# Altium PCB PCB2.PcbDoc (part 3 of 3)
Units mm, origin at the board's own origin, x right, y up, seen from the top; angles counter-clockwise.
Board outline 277.37 x 238.38 mm, 2 copper layers (Top Layer, Bottom Layer); 139 components, 149 nets, 593 pads, 86 vias.
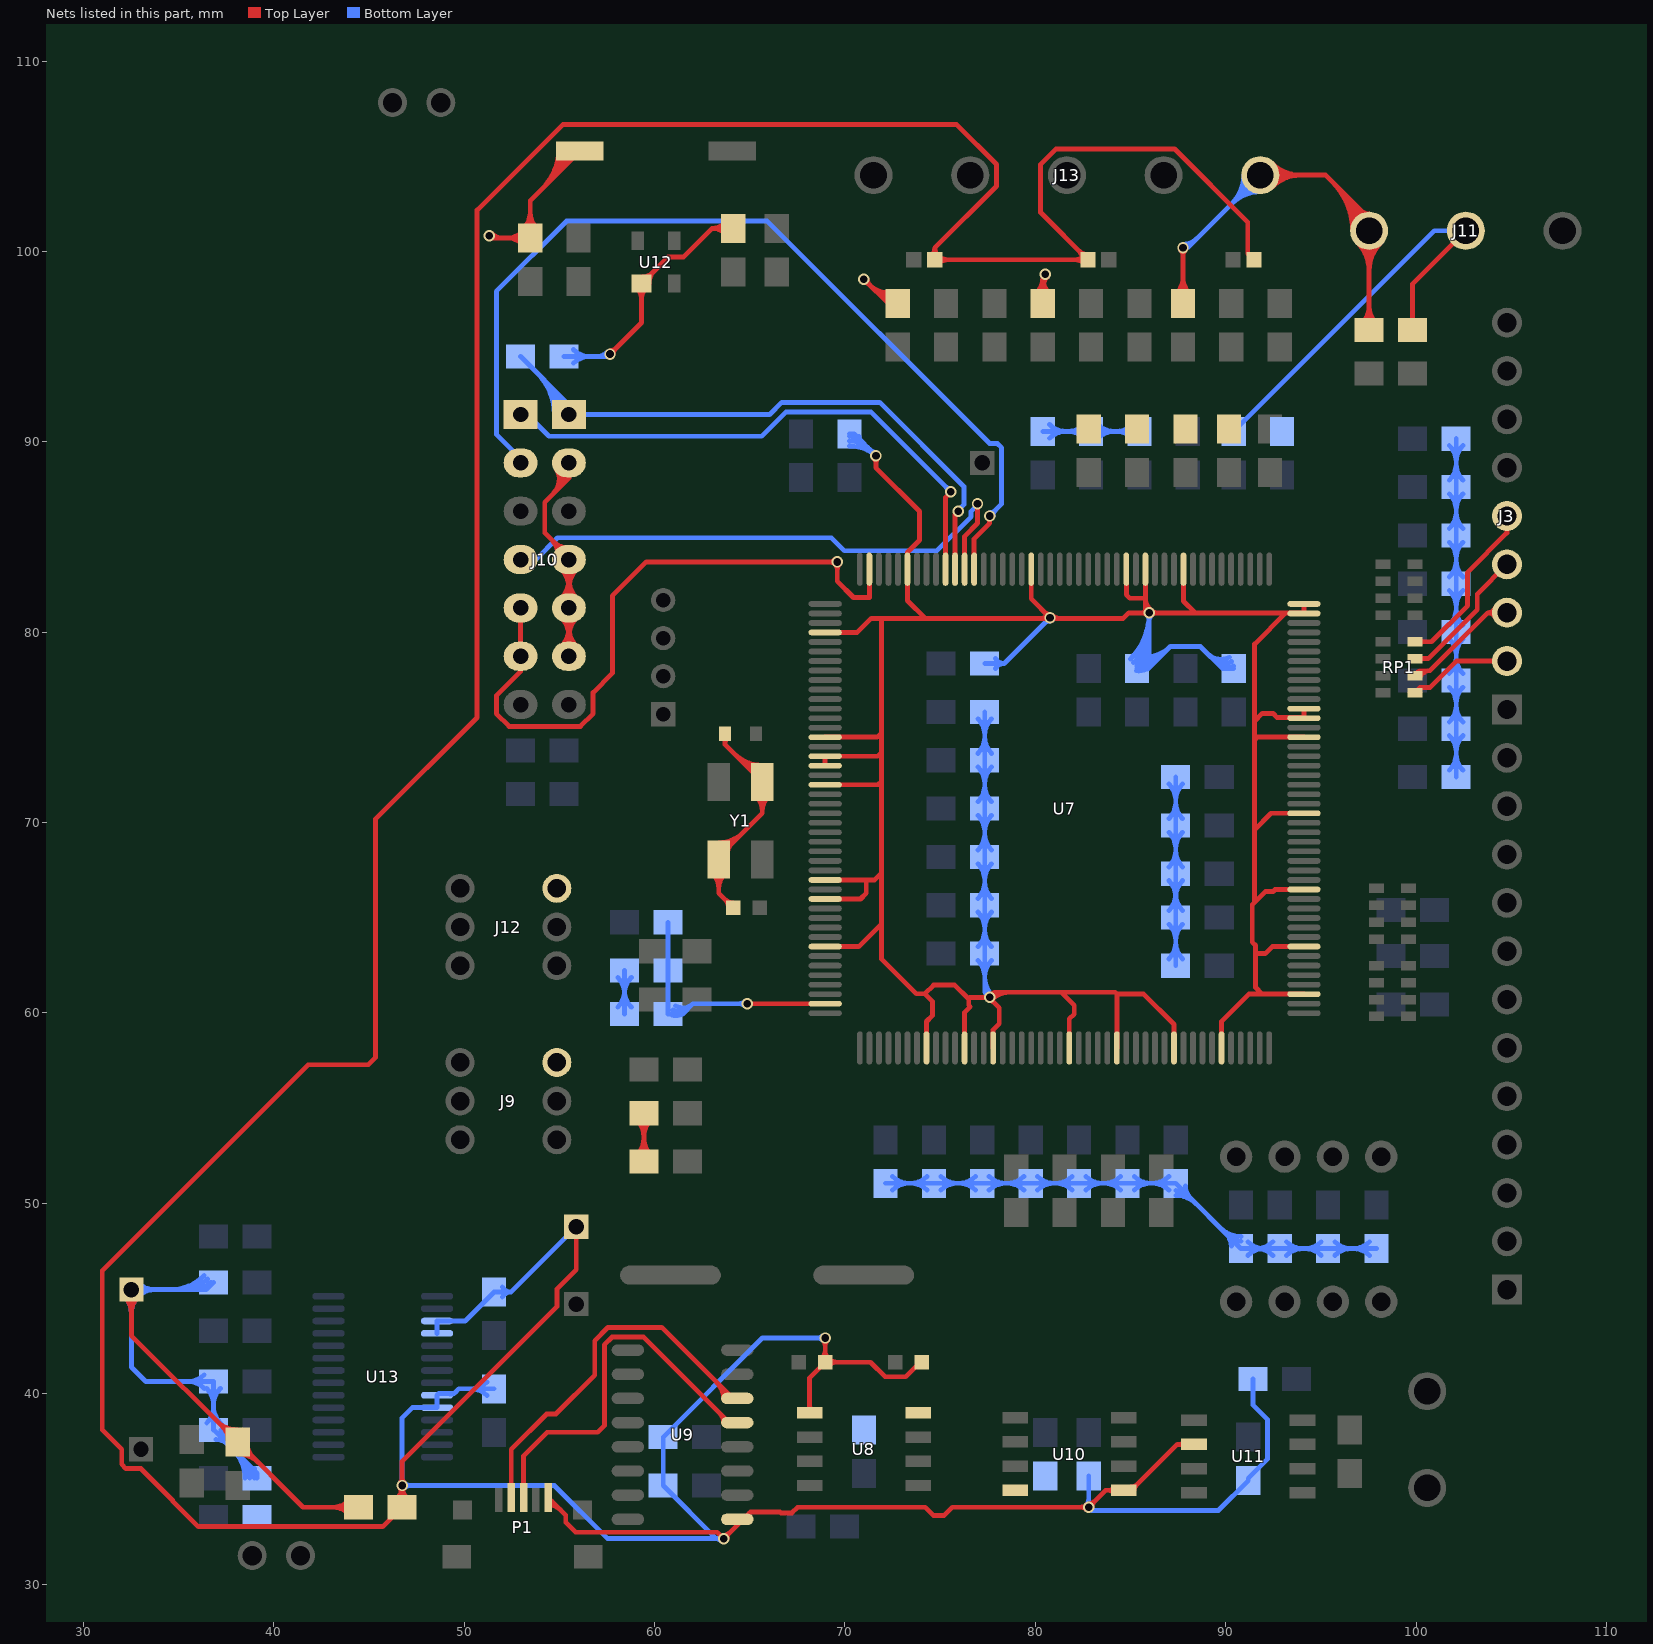
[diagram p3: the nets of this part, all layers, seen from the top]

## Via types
v1: diameter 0.6, hole 0.4, Top Layer to Bottom Layer, 86 vias

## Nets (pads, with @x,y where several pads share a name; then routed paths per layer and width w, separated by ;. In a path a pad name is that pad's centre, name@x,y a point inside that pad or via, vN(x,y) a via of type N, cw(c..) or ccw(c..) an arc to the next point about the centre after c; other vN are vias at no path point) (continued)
SN1: 3.1 C35.2 C37.2 C41.1 C42.1 C43.2 C47.2 C56.1 C64.1 D9.2 D10.2 D11.2 P1.5 R25.1 R59.1 U8.5 U9.1 U10.5 U11.2 U13.3 U13.4 U13.9 U13.10 | length 340.2
  Top Layer w0.254: R59.1@46.396,34.413 ccw(c45.704,35.179) v1(46.736,35.179) ; 46.736,35.814 v1(46.736,35.179) ; R59.1@47.076,34.413 cw(c47.768,35.179) v1(46.736,35.179) ; P1.5@54.416,34.544 55.335,33.625 55.335,33.236 55.851,32.72 63.292,32.72 v1(63.627,32.385) 65.024,33.782 ; 3.1@55.88,48.768 55.88,46.513 54.864,45.497 54.864,44.577 46.736,36.449 v1(46.736,35.179) ; U8.5@68.143,38.989 68.143,40.838 C41.1@68.961,41.656 ; v1(68.961,42.926) C41.1@68.961,41.656 ; C42.1@74.041,41.656 73.945,41.656 73.183,40.894 72.105,40.894 71.343,41.656 C41.1@68.961,41.656 ; U11.2@88.336,37.338 87.459,37.338 85.046,34.925 U10.5@84.638,34.925 83.693,34.925 v1(82.804,34.036) 75.639,34.036 75.212,33.609 74.648,33.609 74.221,34.036 67.511,34.036 67.211,33.736 66.647,33.736 66.601,33.782 65.024,33.782 ; D11.2@91.482,99.568 91.163,99.887 91.163,101.544 87.313,105.394 81.089,105.394 80.28,104.585 80.28,102.05 D10.2@82.762,99.568 D9.2@74.718,99.568 74.718,100.197 ; v1@46.614,35.301 ccw(c46.318,35.597) 46.736,35.597 ; v1@46.614,35.301 ccw(c46.318,35.597) 46.736,35.597 ; v1@46.614,35.301 ccw(c46.318,35.597) 46.736,35.597 ; v1@46.614,35.301 ccw(c46.318,35.597) 46.736,35.597 ; 46.736,34.761 cw(c47.154,34.761) 46.858,35.057 ccw(c47.154,34.761) 46.736,34.761 ; 46.736,34.761 ccw(c46.318,34.761) 46.614,35.057 cw(c46.318,34.761) 46.736,34.761 ; v1(46.736,35.179) R59.1@46.736,34.036 45.72,33.02 36.037,33.02 34.671,34.386 34.671,34.417 33.02,36.068 32.227,36.068 32.004,36.291 32.004,37.084 30.988,38.1 30.988,46.469 41.8,57.281 44.965,57.281 45.335,57.651 45.335,70.185 50.673,75.523 50.673,102.174 55.171,106.672 75.875,106.672 77.962,104.585 77.962,103.441 74.718,100.197 ; 46.736,35.597 ccw(c47.154,35.597) v1@46.858,35.301 ; 46.736,35.597 ccw(c47.154,35.597) v1@46.858,35.301 ; 46.736,35.597 ccw(c47.154,35.597) v1@46.858,35.301 ; 46.736,35.597 ccw(c47.154,35.597) v1@46.858,35.301 ; 63.922,32.68 cw(c63.627,32.976) 63.627,32.558 ccw(c63.627,32.976) 63.922,32.68 ; 63.922,32.68 ccw(c64.218,32.385) 63.8,32.385 cw(c64.218,32.385) 63.922,32.68 ; 65.024,33.782 ccw(c65.158,33.648) 65.019,33.519 cw(c65.158,33.648) 65.024,33.782 ; 68.143,39.407 cw(c67.725,39.407) 68.021,39.111 ccw(c67.725,39.407) 68.143,39.407 ; 68.143,39.407 ccw(c68.561,39.407) 68.265,39.111 cw(c68.561,39.407) 68.143,39.407 ; 68.961,42.269 cw(c68.348,42.269) 68.781,41.836 ccw(c68.348,42.269) 68.961,42.269 ; 68.961,42.269 ccw(c69.574,42.269) C41.1@69.141,41.836 ; 68.961,42.269 ccw(c69.574,42.269) C41.1@69.141,41.836 ; 68.961,42.508 cw(c69.379,42.508) 69.083,42.804 ccw(c69.379,42.508) 68.961,42.508 ; 68.961,42.508 ccw(c68.543,42.508) 68.839,42.804 cw(c68.543,42.508) 68.961,42.508 ; C41.1@69.141,41.836 ccw(c69.574,42.269) 69.574,41.656 ; C41.1@69.141,41.836 ccw(c69.574,42.269) 69.574,41.656 ; 69.574,41.656 ccw(c69.574,41.043) 69.141,41.476 cw(c69.574,41.043) 69.574,41.656 ; 74.718,100.197 cw(c74.13,100.197) 74.532,99.767 ccw(c74.13,100.197) 74.718,100.197 ; 74.718,100.197 ccw(c75.306,100.197) 74.904,99.767 cw(c75.306,100.197) 74.718,100.197 ; 75.377,99.568 cw(c75.377,100.227) 74.911,99.761 ccw(c75.377,100.227) 75.377,99.568 ; 75.377,99.568 ccw(c75.377,98.909) 74.911,99.375 cw(c75.377,98.909) 75.377,99.568 ; 82.103,99.568 cw(c82.103,98.909) 82.569,99.375 ccw(c82.103,98.909) 82.103,99.568 ; 82.103,99.568 ccw(c82.103,100.227) 82.569,99.761 cw(c82.103,100.227) 82.103,99.568 ; 82.296,100.034 cw(c81.83,99.568) 82.489,99.568 ccw(c81.83,99.568) 82.296,100.034 ; 82.296,100.034 ccw(c82.762,100.5) 82.762,99.841 cw(c82.762,100.5) 82.296,100.034 ; 82.386,34.036 cw(c82.386,33.618) 82.682,33.914 ccw(c82.386,33.618) 82.386,34.036 ; 82.386,34.036 ccw(c82.386,34.454) 82.682,34.158 cw(c82.386,34.454) 82.386,34.036 ; 83.099,34.331 cw(c82.804,34.627) 82.804,34.209 ccw(c82.804,34.627) 83.099,34.331 ; 83.099,34.331 ccw(c83.395,34.036) 82.977,34.036 cw(c83.395,34.036) 83.099,34.331 ; 83.845,34.925 cw(c83.845,34.507) 84.141,34.803 ccw(c83.845,34.507) 83.845,34.925 ; 83.845,34.925 ccw(c83.845,35.343) 84.141,35.047 cw(c83.845,35.343) 83.845,34.925 ; 87.543,37.338 cw(c87.543,36.92) 87.839,37.216 ccw(c87.543,36.92) 87.543,37.338 ; 87.543,37.338 ccw(c87.543,37.756) 87.839,37.46 cw(c87.543,37.756) 87.543,37.338 ; P1.5@54.416,34.163 cw(c54.416,33.243) 55.066,33.894 ccw(c54.416,33.243) P1.5@54.416,34.163 ; P1.5@54.416,34.417 cw(c54.416,34.11) 54.633,34.327 ccw(c54.416,34.11) P1.5@54.416,34.417 ; U10.5@85.013,35.098 ccw(c85.013,35.596) 85.365,35.244 cw(c85.013,35.596) U10.5@85.013,35.098 ; U10.5@85.186,34.925 cw(c85.523,34.925) 85.285,35.163 ccw(c85.523,34.925) U10.5@85.186,34.925
  Bottom Layer w0.254: U13.4@48.57,43.169 U13.3@48.57,43.819 50.042,43.819 C56.1@51.562,45.339 52.451,45.339 ; C64.1@51.562,40.259 49.721,40.259 49.475,40.013 48.664,40.013 U13.9@48.57,39.919 U13.10@48.57,39.269 47.27,39.269 46.736,38.735 v1(46.736,35.179) 54.737,35.179 57.531,32.385 63.246,32.385 ; 3.1@55.88,48.768 52.451,45.339 ; v1(63.627,32.385) 63.246,32.385 ; v1(68.961,42.926) 65.659,42.926 C35.2@60.452,37.719 C37.2@60.452,35.179 63.246,32.385 ; C47.2@82.804,35.687 v1(82.804,34.036) 82.977,33.863 89.616,33.863 C43.2@91.186,35.433 91.186,35.56 92.202,36.576 92.202,38.639 91.44,39.401 R25.1@91.44,40.767 ; 46.736,35.597 cw(c46.318,35.597) 46.614,35.301 ccw(c46.318,35.597) 46.736,35.597 ; 46.736,35.597 ccw(c47.154,35.597) v1@46.858,35.301 ; 46.736,35.597 ccw(c47.154,35.597) v1@46.858,35.301 ; v1@46.858,35.301 ccw(c47.154,35.597) 47.154,35.179 ; v1@46.858,35.301 ccw(c47.154,35.597) 47.154,35.179 ; 47.154,35.179 ccw(c47.154,34.761) 46.858,35.057 cw(c47.154,34.761) 47.154,35.179 ; 50.336,40.259 cw(c50.336,39.033) 51.203,39.9 ccw(c50.336,39.033) 50.336,40.259 ; 50.336,40.259 ccw(c50.336,41.485) 51.203,40.618 cw(c50.336,41.485) 50.336,40.259 ; 52.451,45.339 cw(c52.451,45.863) 52,45.597 ccw(c52.451,45.863) 52.451,45.339 ; 52.451,45.339 ccw(c52.451,44.815) 52,45.081 cw(c52.451,44.815) 52.451,45.339 ; 63.209,32.385 cw(c63.209,31.967) 63.505,32.263 ccw(c63.209,31.967) 63.209,32.385 ; 63.209,32.385 ccw(c63.209,32.803) 63.505,32.507 cw(c63.209,32.803) 63.209,32.385 ; 68.543,42.926 cw(c68.543,42.508) 68.839,42.804 ccw(c68.543,42.508) 68.543,42.926 ; 68.543,42.926 ccw(c68.543,43.344) 68.839,43.048 cw(c68.543,43.344) 68.543,42.926 ; 82.804,34.454 cw(c82.386,34.454) 82.682,34.158 ccw(c82.386,34.454) 82.804,34.454 ; 82.804,34.454 ccw(c83.222,34.454) 82.926,34.158 cw(c83.222,34.454) 82.804,34.454 ; U13.9@49.245,39.967 ccw(c49.245,40.412) 49.56,40.097 cw(c49.245,40.412) U13.9@49.245,39.967
SO1: J3.2 RP1.1 | length 5.9
  Top Layer w0.254: RP1.1@99.949,76.835 100.207,77.093 ; J3.2@104.775,78.486 102.123,78.486 100.73,77.093 100.207,77.093 ; 100.207,77.093 ccw(c100.304,76.996) 100.196,76.911 cw(c100.304,76.996) 100.207,77.093
SO2: J3.3 RP1.2 | length 10.7
  Top Layer w0.254: RP1.2@99.949,77.724 100.207,77.982 ; J3.3@104.775,81.026 103.774,81.026 ; 100.207,77.982 ccw(c100.304,77.885) 100.196,77.8 cw(c100.304,77.885) 100.207,77.982 ; 100.207,77.982 100.73,77.982 ; 100.73,77.982 ccw(c100.73,77.392) 100.208,77.667 cw(c100.73,77.392) 100.73,77.982 ; 100.73,77.982 103.774,81.026 ; 103.774,81.026 cw(c103.774,80.598) 104.168,80.766 ccw(c103.774,80.598) 103.774,81.026 ; 103.774,81.026 ccw(c103.774,81.454) 104.168,81.286 cw(c103.774,81.454) 103.774,81.026 ; RP1.2@99.983,77.785 cw(c100.309,77.613) 100.309,77.982 ccw(c100.309,77.613) RP1.2@99.983,77.785
SO3: J3.4 RP1.3 | length 8.3
  Top Layer w0.254: RP1.3@99.949,78.613 100.643,78.613 103.217,81.187 103.217,82.008 J3.4@104.775,83.566 ; 100.396,78.613 cw(c100.396,78.91) 100.186,78.7 ccw(c100.396,78.91) 100.396,78.613 ; 100.396,78.613 ccw(c100.396,78.316) 100.186,78.526 cw(c100.396,78.316) 100.396,78.613
SPEED: C54.2 J11.2 R23.1 | length 22.9
  Top Layer w0.254: C54.2@99.822,95.885 99.822,98.298 J11.2@102.616,101.092
  Bottom Layer w0.254: R23.1@90.424,90.551 100.965,101.092 J11.2@102.616,101.092
START: C55.2 R44.2 R45.2 U7.131 | length 20
  Top Layer w0.254: v1(64.86,60.489) U7.131@68.959,60.489
  Bottom Layer w0.254: R44.2@60.706,64.77 C55.2@60.706,62.23 R45.2@60.706,59.944 61.468,59.944 62.013,60.489 ; v1(64.86,60.489) 62.013,60.489 ; 62.013,60.489 cw(c61.484,61.018) 61.096,60.378 ccw(c61.484,61.018) 62.013,60.489 ; 64.442,60.489 cw(c64.442,60.071) 64.738,60.367 ccw(c64.442,60.071) 64.442,60.489 ; 64.442,60.489 ccw(c64.442,60.907) 64.738,60.611 cw(c64.442,60.907) 64.442,60.489 ; R45.2@60.833,59.944 ccw(c61.139,60.448) 61.555,60.031 cw(c61.139,60.448) R45.2@60.833,59.944 ; R45.2@60.965,60.161 ccw(c61.311,60.733) 61.784,60.26 cw(c61.311,60.733) R45.2@60.965,60.161
T\R\S\T\N\: J10.2 R28.1 U7.78 | length 44.2
  Top Layer w0.254: U7.78@75.784,83.314 v1@75.784,86.198
  Bottom Layer w0.254: R28.1@52.959,94.488 J10.2@55.499,91.948 ; v1(75.946,86.36) 75.946,86.395 76.246,86.695 76.246,87.658 71.829,92.075 66.688,92.075 66.053,91.44 J10.2@55.499,91.44 ; J10.2@55.499,91.44 ccw(c54.273,91.44) 55.14,92.307 cw(c54.273,91.44) J10.2@55.499,91.44 ; 53.839,93.608 cw(c51.671,91.44) 54.737,91.44 ccw(c51.671,91.44) 53.839,93.608 ; 54.273,93.174 cw(c52.538,91.44) 54.991,91.44 ccw(c52.538,91.44) 54.273,93.174 ; 54.706,92.741 cw(c53.405,91.44) 55.245,91.44 ccw(c53.405,91.44) 54.706,92.741
TCK: J10.9 J10.11 U7.87 | length 38
  Top Layer w0.254: J10.9@52.959,81.28 J10.11@52.959,78.74 52.959,77.943 51.689,76.673 51.689,75.727 52.359,75.057 56.099,75.057 56.769,75.727 56.769,76.83 57.785,77.846 57.785,81.915 59.563,83.693 v1(69.596,83.693) 69.596,82.677 70.448,81.825 71.284,81.825 U7.87@71.284,83.314 ; 69.178,83.693 cw(c69.178,83.275) v1@69.474,83.571 ; 69.178,83.693 ccw(c69.178,84.111) 69.474,83.815 cw(c69.178,84.111) 69.178,83.693 ; 69.178,83.693 cw(c69.178,83.275) v1@69.474,83.571 ; v1@69.474,83.571 cw(c69.178,83.275) 69.596,83.275 ; v1@69.474,83.571 cw(c69.178,83.275) 69.596,83.275 ; 69.596,83.275 cw(c70.014,83.275) 69.718,83.571 ccw(c70.014,83.275) 69.596,83.275
TDI: J10.3 U7.76 | length 50.8
  Top Layer w0.254: U7.76@76.784,83.314 76.784,84.912 77.597,85.725 v1(77.597,86.106)
  Bottom Layer w0.254: J10.3@52.959,88.9 52.959,89.123 51.689,90.393 51.689,97.917 55.372,101.6 65.913,101.6 77.597,89.916 78.009,89.916 78.232,89.693 78.232,86.741 v1(77.597,86.106) ; 77.892,86.401 cw(c77.597,86.697) 77.597,86.279 ccw(c77.597,86.697) 77.892,86.401 ; 77.892,86.401 ccw(c78.188,86.106) 77.77,86.106 cw(c78.188,86.106) 77.892,86.401
TDO: J10.7 U7.77 | length 29.7
  Top Layer w0.254: U7.77@76.284,83.314 76.284,85.047 76.962,85.725 v1(76.962,86.741)
  Bottom Layer w0.254: J10.7@52.959,83.82 53.756,83.82 54.899,84.963 69.289,84.963 69.97,84.282 74.831,84.282 76.627,86.078 76.627,86.358 76.962,86.693 v1(76.962,86.741)
TEMP: J3.5 RP1.4 | length 10
  Top Layer w0.254: RP1.4@99.949,79.502 100.813,79.502 102.709,81.398 102.709,83.152 104.775,85.218 J3.5@104.775,86.106 ; 100.396,79.502 cw(c100.396,79.799) 100.186,79.589 ccw(c100.396,79.799) 100.396,79.502 ; 100.396,79.502 ccw(c100.396,79.205) 100.186,79.415 cw(c100.396,79.205) 100.396,79.502
TMS: J10.1 U7.79 | length 30.8
  Top Layer w0.254: U7.79@75.284,83.314 75.284,87.095 v1(75.565,87.376)
  Bottom Layer w0.254: J10.1@52.959,91.44 53.309,91.44 54.452,90.297 65.628,90.297 66.898,91.567 71.374,91.567 v1(75.565,87.376) ; 75.27,87.671 cw(c74.974,87.376) 75.392,87.376 ccw(c74.974,87.376) 75.27,87.671 ; 75.27,87.671 ccw(c75.565,87.967) 75.565,87.549 cw(c75.565,87.967) 75.27,87.671
UD+: P1.3 U9.5 | length 21.5
  Top Layer w0.254: P1.3@53.116,34.544 53.116,36.733 54.356,37.973 57.015,37.973 57.362,38.32 57.362,42.573 57.761,42.972 59.425,42.972 63.916,38.481 U9.5@64.343,38.481 ; 63.411,38.986 cw(c62.905,38.481) 63.62,38.481 ccw(c62.905,38.481) 63.411,38.986
UD-: P1.2 U9.6 | length 22.3
  Top Layer w0.254: P1.2@52.466,34.544 52.466,37.076 54.325,38.935 54.815,38.935 56.854,40.974 56.854,42.783 57.551,43.48 60.371,43.48 64.1,39.751 U9.6@64.343,39.751 ; 63.281,40.57 cw(c62.461,39.751) 63.62,39.751 ccw(c62.461,39.751) 63.281,40.57 ; 63.714,40.137 cw(c63.329,39.751) 63.874,39.751 ccw(c63.329,39.751) 63.714,40.137
VSS: 5.1 C25.1 C26.1 C27.2 C28.1 C29.1 C30.1 C31.1 C32.1 C33.1 C34.2 C36.1 C38.1 C39.2 C40.2 C44.1 C45.2 C46.1 C48.1 C49.1 C50.2 C51.2 C52.2 C53.1 C54.1 C55.1 C57.2 C58.1 C59.1 C60.1 C61.1 C62.1 C63.1 C65.2 C66.1 C67.1 C68.2 C69.1 C70.1 C71.1 C72.1 C73.1 C74.1 C75.1 C76.1 C77.1 C78.1 C79.1 C80.1 C81.1 C82.1 C83.1 C84.1 C85.1 D12.2 J9.1 J10.4 J10.8 J10.10 J10.12 J11.1 J12.1 J13.5 R28.2 R33.1 R34.1 R38.1 R39.1 R40.1 R41.1 R45.1 R47.1 R59.2 S1.2 U7.3 U7.8 U7.14 U7.22 U7.30 U7.32 U7.33 U7.43 U7.44 U7.54 U7.58 U7.60 U7.70 U7.83 U7.92 U7.103 U7.105 U7.106 U7.108 U7.118 U7.120 U7.125 U7.140 U7.144 U7.147 U7.155 U7.160 U7.166 U7.171 U8.4 U10.4 U12.1 Y1.2 Y1.4 | length 884.1
  Top Layer w0.254: 5.1@32.512,45.466 32.512,43.053 D12.2@38.1,37.465 41.529,34.036 R59.2@44.45,34.036 ; R59.2@43.964,33.677 ccw(c43.097,32.81) 43.097,34.036 ccw(c43.097,35.262) R59.2@43.964,34.395 ; v1@51.435,100.711 C52.2@53.467,100.711 53.467,102.679 S1.2@56.071,105.283 ; J10.12@55.499,78.74 J10.10@55.499,81.28 J10.8@55.499,83.82 55.499,83.947 54.229,85.217 54.229,86.833 55.499,88.103 J10.4@55.499,88.9 ; v1(57.658,94.615) 59.311,96.268 U12.1@59.311,98.316 60.705,99.71 61.514,99.71 63.023,101.219 ; C49.1@59.436,52.197 R33.1@59.436,54.737 ; C40.2@63.703,74.676 63.703,74.092 Y1.4@65.659,72.136 65.659,70.492 63.373,68.206 Y1.2@63.373,68.072 63.373,66.294 C39.2@64.135,65.532 ; C53.1@64.135,101.219 63.023,101.219 ; U7.125@68.959,63.489 70.728,63.489 71.928,64.689 ; U7.120@68.959,65.989 70.815,65.989 71.12,66.294 71.12,66.883 ; U7.118@68.959,66.989 71.561,66.989 71.928,67.356 ; U7.108@68.959,71.989 71.735,71.989 71.928,72.182 ; U7.106@68.959,72.989 U7.105@68.959,73.489 71.711,73.489 71.928,73.706 ; U7.103@68.959,74.489 71.695,74.489 71.928,74.722 ; U7.92@68.959,79.989 70.644,79.989 ; 70.652,79.997 71.381,80.726 71.882,80.726 ; v1(70.993,98.552) 72.263,97.282 C61.1@72.771,97.282 ; v1(71.628,89.281) 71.628,88.646 73.914,86.36 73.914,84.836 73.284,84.206 U7.83@73.284,83.314 73.284,81.656 74.214,80.726 ; U7.140@74.284,58.164 74.284,59.552 74.595,59.863 74.595,60.607 74.196,61.006 ; U7.144@76.284,58.164 76.284,60.028 76.581,60.325 76.5,60.406 76.5,60.734 75.766,61.468 74.658,61.468 74.196,61.006 ; 76.577,60.811 v1@77.566,60.811 ; U7.147@77.784,58.164 77.784,59.115 78.105,59.436 78.105,60.272 v1@77.566,60.811 ; U7.70@79.784,83.314 79.784,81.76 v1(80.772,80.772) v1@80.818,80.726 ; C62.1@80.391,97.282 v1@80.391,98.679 ; v1@80.991,80.726 81.915,80.726 ; U7.155@81.784,58.164 81.784,59.686 82.042,59.944 82.042,60.399 81.354,61.087 ; U7.160@84.284,58.164 84.284,61.004 ; U7.60@84.784,83.314 84.784,81.967 84.963,81.788 85.784,81.788 ; U7.58@85.784,83.314 85.784,81.788 ; U7.166@87.284,58.164 87.284,59.401 85.681,61.004 84.284,61.004 ; C63.1@87.757,97.282 v1(87.757,100.203) ; U7.54@87.784,83.314 87.784,81.634 88.398,81.02 ; U7.171@89.784,58.164 89.784,59.558 91.215,60.989 91.845,60.989 ; J13.5@91.821,104.013 95.25,104.013 97.536,101.727 J11.1@97.536,101.092 C54.1@97.536,95.885 ; 92.59,66.481 92.484,66.375 92.075,66.375 91.526,65.827 ; 92.598,66.489 U7.14@94.109,66.489 ; U7.3@94.109,60.989 91.919,60.989 91.567,61.341 91.567,63.119 ; U7.8@94.109,63.489 92.445,63.489 92.075,63.119 91.567,63.119 ; U7.22@94.109,70.489 92.379,70.489 91.521,69.631 ; U7.30@94.109,74.489 91.669,74.489 91.521,74.341 ; U7.33@94.109,75.958 94.109,75.52 92.702,75.52 92.484,75.738 91.92,75.738 91.521,75.339 ; U7.44@94.109,81.489 94.109,81.02 93.164,81.02 ; 95.597,103.666 cw(c93.022,101.092) J11.1@96.663,101.092 ; 96.03,103.233 cw(c93.89,101.092) J11.1@96.917,101.092 ; 96.464,102.799 cw(c94.757,101.092) J11.1@97.171,101.092 ; 96.897,102.366 cw(c95.624,101.092) J11.1@97.425,101.092 ; J11.1@96.919,100.475 cw(c95.428,98.984) 97.536,98.984 cw(c99.644,98.984) J11.1@98.153,100.475 ; J11.1@97.098,100.654 cw(c96.042,99.598) 97.536,99.598 cw(c99.03,99.598) J11.1@97.974,100.654 ; 97.13,102.133 ccw(c97.536,102.54) J11.1@97.536,101.965 ; 32.512,44.24 cw(c33.738,44.24) 32.871,45.107 ccw(c33.738,44.24) 32.512,44.24 ; 32.512,44.24 ccw(c31.286,44.24) 32.153,45.107 cw(c31.286,44.24) 32.512,44.24 ; 52.241,100.711 cw(c52.241,99.485) 53.108,100.352 ccw(c52.241,99.485) 52.241,100.711 ; 52.241,100.711 ccw(c52.241,101.937) 53.108,101.07 cw(c52.241,101.937) 52.241,100.711 ; 53.467,102.064 cw(c52.241,102.064) 53.108,101.197 ccw(c52.241,102.064) 53.467,102.064 ; 53.467,102.064 ccw(c54.693,102.064) 53.826,101.197 cw(c54.693,102.064) 53.467,102.064 ; 55.499,79.66 cw(c54.579,79.66) 55.23,79.009 ccw(c54.579,79.66) 55.499,79.66 ; 55.499,79.66 ccw(c56.419,79.66) 55.768,79.009 cw(c56.419,79.66) 55.499,79.66 ; 55.499,79.747 cw(c57.032,79.747) 55.948,80.831 ccw(c57.032,79.747) 55.499,79.747 ; 55.499,79.747 ccw(c53.966,79.747) 55.05,80.831 cw(c53.966,79.747) 55.499,79.747 ; 55.499,80.273 cw(c53.966,80.273) 55.05,79.189 ccw(c53.966,80.273) 55.499,80.273 ; 55.499,80.273 ccw(c57.032,80.273) 55.948,79.189 cw(c57.032,80.273) 55.499,80.273 ; 55.499,80.36 cw(c56.419,80.36) 55.768,81.011 ccw(c56.419,80.36) 55.499,80.36 ; 55.499,80.36 ccw(c54.579,80.36) 55.23,81.011 cw(c54.579,80.36) 55.499,80.36 ; 55.499,82.2 cw(c54.579,82.2) 55.23,81.549 ccw(c54.579,82.2) 55.499,82.2 ; 55.499,82.2 ccw(c56.419,82.2) 55.768,81.549 cw(c56.419,82.2) 55.499,82.2 ; 55.499,82.287 cw(c57.032,82.287) 55.948,83.371 ccw(c57.032,82.287) 55.499,82.287 ; 55.499,82.287 ccw(c53.966,82.287) 55.05,83.371 cw(c53.966,82.287) 55.499,82.287 ; 55.499,82.813 cw(c53.966,82.813) 55.05,81.729 ccw(c53.966,82.813) 55.499,82.813 ; 55.499,82.813 ccw(c57.032,82.813) 55.948,81.729 cw(c57.032,82.813) 55.499,82.813 ; 55.499,82.9 cw(c56.419,82.9) 55.768,83.551 ccw(c56.419,82.9) 55.499,82.9 ; 55.499,82.9 ccw(c54.579,82.9) 55.23,83.551 cw(c54.579,82.9) 55.499,82.9 ; 57.953,94.91 cw(c57.658,95.206) 57.658,94.788 ccw(c57.658,95.206) 57.953,94.91 ; 57.953,94.91 ccw(c58.249,94.615) 57.831,94.615 cw(c58.249,94.615) 57.953,94.91 ; 59.311,97.476 cw(c60.151,97.476) 59.557,98.07 ccw(c60.151,97.476) 59.311,97.476 ; 59.311,97.476 ccw(c58.471,97.476) 59.065,98.07 cw(c58.471,97.476) 59.311,97.476 ; 59.436,53.423 cw(c58.21,53.423) 59.077,52.556 ccw(c58.21,53.423) 59.436,53.423 ; 59.436,53.423 ccw(c60.662,53.423) 59.795,52.556 cw(c60.662,53.423) 59.436,53.423 ; 59.436,53.511 cw(c60.662,53.511) 59.795,54.378 ccw(c60.662,53.511) 59.436,53.511 ; 59.436,53.511 ccw(c58.21,53.511) 59.077,54.378 cw(c58.21,53.511) 59.436,53.511 ; 63.023,101.219 cw(c63.023,100.256) 63.751,100.886 ccw(c63.023,100.256) 63.023,101.219 ; 63.023,101.219 ccw(c63.023,102.182) 63.751,101.552 cw(c63.023,102.182) 63.023,101.219 ; 63.373,66.53 cw(c64.515,66.53) 63.707,67.338 ccw(c64.515,66.53) 63.373,66.53 ; 63.373,66.53 ccw(c62.231,66.53) 63.039,67.338 cw(c62.231,66.53) 63.373,66.53 ; 63.701,65.966 cw(c63.268,65.532) 63.881,65.532 ccw(c63.268,65.532) 63.701,65.966 ; 63.701,65.966 ccw(c64.135,66.399) 64.135,65.786 cw(c64.135,66.399) 63.701,65.966 ; 63.703,74.153 cw(c64.163,74.153) 63.838,74.478 ccw(c64.163,74.153) 63.703,74.153 ; 63.703,74.153 ccw(c63.243,74.153) 63.568,74.478 cw(c63.243,74.153) 63.703,74.153 ; 65.659,70.594 cw(c66.801,70.594) 65.993,71.402 ccw(c66.801,70.594) 65.659,70.594 ; 65.659,70.594 ccw(c64.517,70.594) 65.325,71.402 cw(c64.517,70.594) 65.659,70.594 ; 71.288,98.257 cw(c71.584,98.552) 71.166,98.552 ccw(c71.584,98.552) 71.288,98.257 ; 71.288,98.257 ccw(c70.993,97.961) 70.993,98.379 cw(c70.993,97.961) 71.288,98.257 ; 71.628,88.863 cw(c72.046,88.863) 71.75,89.159 ccw(c72.046,88.863) 71.628,88.863 ; 71.628,88.863 ccw(c71.21,88.863) 71.506,89.159 cw(c71.21,88.863) 71.628,88.863 ; 71.882,80.726 71.928,80.68 71.928,74.722 ; 71.882,80.726 74.214,80.726 ; 71.928,64.689 71.928,62.819 73.741,61.006 74.196,61.006 ; 71.928,64.689 71.928,67.356 ; 71.928,67.356 71.928,72.182 ; 71.928,72.182 71.928,73.706 ; 71.928,73.706 71.928,74.722 ; 74.214,80.726 v1@80.818,80.726 ; v1@77.566,60.811 77.842,61.087 81.354,61.087 ; v1@80.391,98.635 cw(c79.165,98.635) 80.032,97.768 ccw(c79.165,98.635) v1@80.391,98.635 ; v1@80.391,98.635 ccw(c81.617,98.635) 80.75,97.768 cw(c81.617,98.635) v1@80.391,98.635 ; 80.477,81.067 cw(c80.181,80.772) 80.599,80.772 ccw(c80.181,80.772) 80.477,81.067 ; 80.477,81.067 ccw(c80.772,81.363) 80.772,80.945 cw(c80.772,81.363) 80.477,81.067 ; v1@80.818,80.726 81.915,80.726 ; v1@80.894,80.65 cw(c81.079,80.465) 81.079,80.726 ; v1@80.894,80.65 cw(c81.079,80.465) 81.079,80.726 ; v1@80.894,80.65 cw(c81.079,80.465) 81.079,80.726 ; v1@80.894,80.65 cw(c81.079,80.465) 81.079,80.726 ; v1@80.894,80.894 ccw(c81.301,81.301) 81.301,80.726 ; v1@80.894,80.894 ccw(c81.301,81.301) 81.301,80.726 ; v1@80.894,80.894 ccw(c81.301,81.301) 81.301,80.726 ; v1@80.894,80.894 ccw(c81.301,81.301) 81.301,80.726 ; 81.354,61.087 84.201,61.087 84.284,61.004 ; 81.915,80.726 84.61,80.726 84.904,81.02 v1@86.112,81.02 ; 85.784,81.788 ccw(c86.584,81.788) 86.087,81.161 cw(c86.584,81.788) 85.784,81.788 ; 85.784,81.788 85.784,81.348 v1@86.112,81.02 ; v1@86.112,81.02 88.398,81.02 ; 87.757,98.635 cw(c86.531,98.635) 87.398,97.768 ccw(c86.531,98.635) 87.757,98.635 ; 87.757,98.635 ccw(c88.983,98.635) 88.116,97.768 cw(c88.983,98.635) 87.757,98.635 ; 87.757,99.785 cw(c88.175,99.785) 87.879,100.081 ccw(c88.175,99.785) 87.757,99.785 ; 87.757,99.785 ccw(c87.339,99.785) 87.635,100.081 cw(c87.339,99.785) 87.757,99.785 ; 88.398,81.02 93.164,81.02 ; 91.521,69.631 91.521,74.341 ; 91.521,69.631 91.521,65.832 91.526,65.827 ; 91.521,74.341 91.521,75.339 ; 91.521,75.339 91.521,79.377 93.164,81.02 ; 91.526,65.827 91.394,65.694 91.394,63.726 91.567,63.553 91.567,63.119 ; 93.315,104.013 cw(c93.315,105.507) 92.259,104.451 ccw(c93.315,105.507) 93.315,104.013 ; 93.315,104.013 ccw(c93.315,102.519) 92.259,103.575 cw(c93.315,102.519) 93.315,104.013 ; 93.929,104.013 cw(c93.929,106.121) 92.438,104.63 ccw(c93.929,106.121) 93.929,104.013 ; 93.929,104.013 ccw(c93.929,101.905) 92.438,103.396 cw(c93.929,101.905) 93.929,104.013 ; 97.536,97.111 cw(c96.31,97.111) 97.177,96.244 ccw(c96.31,97.111) 97.536,97.111 ; 97.536,97.111 ccw(c98.762,97.111) 97.895,96.244 cw(c98.762,97.111) 97.536,97.111 ; 37.016,38.549 ccw(c38.1,39.633) 38.1,38.1 cw(c38.1,39.633) 37.016,38.549 ; 37.323,38.242 cw(c36.672,37.592) 37.592,37.592 ccw(c36.672,37.592) 37.323,38.242 ; 37.45,38.115 ccw(c38.1,38.766) 38.1,37.846 cw(c38.1,38.766) 37.45,38.115 ; D12.2@38.1,36.83 cw(c38.1,35.297) 39.184,36.381 ccw(c38.1,35.297) D12.2@38.1,36.83 ; D12.2@38.1,37.084 cw(c38.1,36.164) 38.75,36.815 ccw(c38.1,36.164) D12.2@38.1,37.084 ; D12.2@38.608,37.338 ccw(c39.528,37.338) 38.877,36.688 cw(c39.528,37.338) D12.2@38.608,37.338 ; v1@51.43,100.96 ccw(c52.032,101.562) 52.032,100.711 cw(c52.032,101.562) v1@51.43,100.96 ; 54.154,103.366 ccw(c52.237,105.283) 54.948,105.283 cw(c52.237,105.283) 54.154,103.366 ; 54.542,84.904 cw(c53.458,83.82) 54.991,83.82 ccw(c53.458,83.82) 54.542,84.904 ; 54.588,103.8 ccw(c53.104,105.283) 55.202,105.283 cw(c53.104,105.283) 54.588,103.8 ; 54.691,87.295 ccw(c53.967,88.019) 54.834,88.563 cw(c53.967,88.019) 54.691,87.295 ; 54.722,84.724 ccw(c55.372,85.375) 55.372,84.455 cw(c55.372,85.375) 54.722,84.724 ; 54.916,87.521 ccw(c54.244,88.193) 55.049,88.698 cw(c54.244,88.193) 54.916,87.521 ; 55.021,104.233 ccw(c53.971,105.283) 55.456,105.283 cw(c53.971,105.283) 55.021,104.233 ; 55.142,87.746 ccw(c54.521,88.366) 55.264,88.833 cw(c54.521,88.366) 55.142,87.746 ; 55.367,87.971 ccw(c54.798,88.54) 55.48,88.967 cw(c54.798,88.54) 55.367,87.971 ; 55.455,104.667 ccw(c54.838,105.283) 55.71,105.283 cw(c54.838,105.283) 55.455,104.667 ; S1.2@55.888,105.1 ccw(c55.706,105.283) 55.964,105.283 cw(c55.706,105.283) S1.2@55.888,105.1 ; U12.1@59.361,98.664 ccw(c59.361,99.383) 59.87,98.875 cw(c59.361,99.383) U12.1@59.361,98.664 ; U12.1@59.709,98.316 cw(c60.67,98.316) 59.99,98.995 ccw(c60.67,98.316) U12.1@59.709,98.316 ; Y1.2@63.373,68.691 ccw(c63.373,69.861) 64.2,69.034 cw(c63.373,69.861) Y1.2@63.373,68.691 ; Y1.2@63.373,68.945 ccw(c63.373,70.728) 64.634,69.467 cw(c63.373,70.728) Y1.2@63.373,68.945 ; Y1.2@63.846,68.472 cw(c64.347,68.472) 63.993,68.826 ccw(c64.347,68.472) Y1.2@63.846,68.472 ; 64.169,73.626 ccw(c65.659,75.117) 65.659,73.009 cw(c65.659,75.117) 64.169,73.626 ; 64.602,73.193 ccw(c65.659,74.249) 65.659,72.755 cw(c65.659,74.249) 64.602,73.193 ; 65.036,72.759 ccw(c65.659,73.382) 65.659,72.501 cw(c65.659,73.382) 65.036,72.759 ; 71.311,98.234 ccw(c72.255,99.179) 72.629,97.897 cw(c72.255,99.179) 71.311,98.234 ; 71.614,97.931 ccw(c72.392,98.709) 72.7,97.653 cw(c72.392,98.709) 71.614,97.931 ; 71.917,97.628 ccw(c72.529,98.239) 72.771,97.409 cw(c72.529,98.239) 71.917,97.628 ; v1@77.54,60.89 cw(c78.015,60.415) 78.015,61.087 ccw(c78.015,60.415) v1@77.54,60.89 ; v1@77.719,60.711 cw(c78.628,59.802) 78.628,61.087 ccw(c78.628,59.802) v1@77.719,60.711 ; 80.243,80.726 ccw(c80.243,81.301) 80.65,80.894 cw(c80.243,81.301) 80.243,80.726 ; 80.391,98.082 cw(c81.242,98.082) 80.64,98.684 ccw(c81.242,98.082) 80.391,98.082 ; 80.465,80.726 cw(c80.465,80.465) 80.65,80.65 ccw(c80.465,80.465) 80.465,80.726 ; 85.547,81.02 ccw(c85.547,81.458) 85.857,81.148 cw(c85.547,81.458) 85.547,81.02 ; 85.576,81.02 cw(c85.576,80.623) 85.857,80.904 ccw(c85.576,80.623) 85.576,81.02 ; 85.784,81.262 ccw(c86.166,81.262) 85.929,80.963 cw(c86.166,81.262) 85.784,81.262 ; v1@86.101,80.904 cw(c86.382,80.623) 86.382,81.02 ccw(c86.382,80.623) v1@86.101,80.904 ; v1@86.101,81.148 ccw(c86.411,81.458) 86.411,81.02 cw(c86.411,81.458) v1@86.101,81.148
  Bottom Layer w0.254: R47.1@36.83,45.847 36.449,45.466 5.1@32.512,45.466 32.512,41.402 33.274,40.64 C57.2@36.83,40.64 C58.1@36.83,38.1 39.116,35.814 C60.1@39.116,35.56 ; R28.2@55.245,94.488 v1@57.531,94.488 ; R45.1@58.42,59.944 C55.1@58.42,62.23 ; C45.2@70.231,90.424 70.485,90.424 v1(71.628,89.281) ; C74.1@72.136,51.054 C83.1@74.676,51.054 C77.1@77.216,51.054 C75.1@79.756,51.054 C85.1@82.296,51.054 C76.1@84.836,51.054 C84.1@87.376,51.054 R38.1@90.805,47.625 R39.1@92.837,47.625 R40.1@95.377,47.625 R41.1@97.917,47.625 ; 77.343,61.087 C73.1@77.343,63.119 C82.1@77.343,65.659 C72.1@77.343,68.199 C71.1@77.343,70.739 C81.1@77.343,73.279 C70.1@77.343,75.819 ; C80.1@77.343,78.359 78.359,78.359 ; C79.1@80.391,90.551 C69.1@82.931,90.551 C44.1@85.471,90.551 ; v1(80.772,80.772) 78.359,78.359 ; v1(85.979,81.026) 85.979,78.74 C34.2@85.344,78.105 85.948,78.105 87.091,79.248 ; C65.2@87.376,62.484 C78.1@87.376,65.024 C66.1@87.376,67.31 C67.1@87.376,69.85 C68.2@87.376,72.39 ; v1(87.757,100.203) 88.011,100.203 J13.5@91.821,104.013 ; C38.1@90.424,78.105 89.82,78.105 88.677,79.248 87.091,79.248 ; C25.1@102.108,72.39 C26.1@102.108,74.93 C27.2@102.108,77.47 C28.1@102.108,80.01 C29.1@102.108,82.55 C30.1@102.108,85.09 C31.1@102.108,87.63 C32.1@102.108,90.17 ; 32.512,44.24 cw(c33.738,44.24) 5.1@32.871,45.107 ; 32.512,44.24 ccw(c31.286,44.24) 32.153,45.107 cw(c31.286,44.24) 32.512,44.24 ; 32.512,44.24 cw(c33.738,44.24) 5.1@32.871,45.107 ; 5.1@32.871,45.107 cw(c33.738,44.24) 33.738,45.466 ; 5.1@32.871,45.107 cw(c33.738,44.24) 33.738,45.466 ; 33.738,45.466 cw(c33.738,46.692) 32.871,45.825 ccw(c33.738,46.692) 33.738,45.466 ; 35.477,40.64 cw(c35.477,39.414) 36.344,40.281 ccw(c35.477,39.414) 35.477,40.64 ; 35.477,40.64 ccw(c35.477,41.866) 36.344,40.999 cw(c35.477,41.866) 35.477,40.64 ; 36.83,39.326 cw(c35.604,39.326) 36.471,38.459 ccw(c35.604,39.326) 36.83,39.326 ; 36.83,39.326 ccw(c38.056,39.326) 37.189,38.459 cw(c38.056,39.326) 36.83,39.326 ; 36.83,39.414 cw(c38.056,39.414) 37.189,40.281 ccw(c38.056,39.414) 36.83,39.414 ; 36.83,39.414 ccw(c35.604,39.414) 36.471,40.281 cw(c35.604,39.414) 36.83,39.414 ; 56.598,94.488 cw(c56.598,95.714) 55.731,94.847 ccw(c56.598,95.714) 56.598,94.488 ; 56.598,94.488 ccw(c56.598,93.262) 55.731,94.129 cw(c56.598,93.262) 56.598,94.488 ; 58.42,61.004 cw(c59.646,61.004) 58.779,61.871 ccw(c59.646,61.004) 58.42,61.004 ; 58.42,61.004 ccw(c57.194,61.004) 58.061,61.871 cw(c57.194,61.004) 58.42,61.004 ; 58.42,61.17 cw(c57.194,61.17) 58.061,60.303 ccw(c57.194,61.17) 58.42,61.17 ; 58.42,61.17 ccw(c59.646,61.17) 58.779,60.303 cw(c59.646,61.17) 58.42,61.17 ; 71.333,89.576 cw(c71.037,89.281) 71.455,89.281 ccw(c71.037,89.281) 71.333,89.576 ; 71.333,89.576 ccw(c71.628,89.872) 71.628,89.454 cw(c71.628,89.872) 71.333,89.576 ; 73.362,51.054 cw(c73.362,52.28) 72.495,51.413 ccw(c73.362,52.28) 73.362,51.054 ; 73.362,51.054 ccw(c73.362,49.828) 72.495,50.695 cw(c73.362,49.828) 73.362,51.054 ; 73.45,51.054 cw(c73.45,49.828) 74.317,50.695 ccw(c73.45,49.828) 73.45,51.054 ; 73.45,51.054 ccw(c73.45,52.28) 74.317,51.413 cw(c73.45,52.28) 73.45,51.054 ; 75.902,51.054 cw(c75.902,52.28) 75.035,51.413 ccw(c75.902,52.28) 75.902,51.054 ; 75.902,51.054 ccw(c75.902,49.828) 75.035,50.695 cw(c75.902,49.828) 75.902,51.054 ; 75.99,51.054 cw(c75.99,49.828) 76.857,50.695 ccw(c75.99,49.828) 75.99,51.054 ; 75.99,51.054 ccw(c75.99,52.28) 76.857,51.413 cw(c75.99,52.28) 75.99,51.054 ; 77.343,61.893 cw(c78.569,61.893) 77.702,62.76 ccw(c78.569,61.893) 77.343,61.893 ; 77.343,61.893 ccw(c76.117,61.893) 76.984,62.76 cw(c76.117,61.893) 77.343,61.893 ; 77.343,64.345 cw(c76.117,64.345) 76.984,63.478 ccw(c76.117,64.345) 77.343,64.345 ; 77.343,64.345 ccw(c78.569,64.345) 77.702,63.478 cw(c78.569,64.345) 77.343,64.345 ; 77.343,64.433 cw(c78.569,64.433) 77.702,65.3 ccw(c78.569,64.433) 77.343,64.433 ; 77.343,64.433 ccw(c76.117,64.433) 76.984,65.3 cw(c76.117,64.433) 77.343,64.433 ; 77.343,66.885 cw(c76.117,66.885) 76.984,66.018 ccw(c76.117,66.885) 77.343,66.885 ; 77.343,66.885 ccw(c78.569,66.885) 77.702,66.018 cw(c78.569,66.885) 77.343,66.885 ; 77.343,66.973 cw(c78.569,66.973) 77.702,67.84 ccw(c78.569,66.973) 77.343,66.973 ; 77.343,66.973 ccw(c76.117,66.973) 76.984,67.84 cw(c76.117,66.973) 77.343,66.973 ; 77.343,69.425 cw(c76.117,69.425) 76.984,68.558 ccw(c76.117,69.425) 77.343,69.425 ; 77.343,69.425 ccw(c78.569,69.425) 77.702,68.558 cw(c78.569,69.425) 77.343,69.425 ; 77.343,69.513 cw(c78.569,69.513) 77.702,70.38 ccw(c78.569,69.513) 77.343,69.513 ; 77.343,69.513 ccw(c76.117,69.513) 76.984,70.38 cw(c76.117,69.513) 77.343,69.513 ; 77.343,71.965 cw(c76.117,71.965) 76.984,71.098 ccw(c76.117,71.965) 77.343,71.965 ; 77.343,71.965 ccw(c78.569,71.965) 77.702,71.098 cw(c78.569,71.965) 77.343,71.965 ; 77.343,72.053 cw(c78.569,72.053) 77.702,72.92 ccw(c78.569,72.053) 77.343,72.053 ; 77.343,72.053 ccw(c76.117,72.053) 76.984,72.92 cw(c76.117,72.053) 77.343,72.053 ; 77.343,74.505 cw(c76.117,74.505) 76.984,73.638 ccw(c76.117,74.505) 77.343,74.505 ; 77.343,74.505 ccw(c78.569,74.505) 77.702,73.638 cw(c78.569,74.505) 77.343,74.505 ; 77.343,74.593 cw(c78.569,74.593) 77.702,75.46 ccw(c78.569,74.593) 77.343,74.593 ; 77.343,74.593 ccw(c76.117,74.593) 76.984,75.46 cw(c76.117,74.593) 77.343,74.593 ; 78.359,78.359 cw(c78.359,78.883) 77.908,78.617 ccw(c78.359,78.883) 78.359,78.359 ; 78.359,78.359 ccw(c78.359,77.835) 77.908,78.101 cw(c78.359,77.835) 78.359,78.359 ; 78.442,51.054 cw(c78.442,52.28) 77.575,51.413 ccw(c78.442,52.28) 78.442,51.054 ; 78.442,51.054 ccw(c78.442,49.828) 77.575,50.695 cw(c78.442,49.828) 78.442,51.054 ; 78.53,51.054 cw(c78.53,49.828) 79.397,50.695 ccw(c78.53,49.828) 78.53,51.054 ; 78.53,51.054 ccw(c78.53,52.28) 79.397,51.413 cw(c78.53,52.28) 78.53,51.054 ; 80.477,80.477 cw(c80.772,80.181) 80.772,80.599 ccw(c80.772,80.181) 80.477,80.477 ; 80.477,80.477 ccw(c80.181,80.772) 80.599,80.772 cw(c80.181,80.772) 80.477,80.477 ; 80.982,51.054 cw(c80.982,52.28) 80.115,51.413 ccw(c80.982,52.28) 80.982,51.054 ; 80.982,51.054 ccw(c80.982,49.828) 80.115,50.695 cw(c80.982,49.828) 80.982,51.054 ; 81.07,51.054 cw(c81.07,49.828) 81.937,50.695 ccw(c81.07,49.828) 81.07,51.054 ; 81.07,51.054 ccw(c81.07,52.28) 81.937,51.413 cw(c81.07,52.28) 81.07,51.054 ; 81.617,90.551 cw(c81.617,91.777) 80.75,90.91 ccw(c81.617,91.777) 81.617,90.551 ; 81.617,90.551 ccw(c81.617,89.325) 80.75,90.192 cw(c81.617,89.325) 81.617,90.551 ; 81.705,90.551 cw(c81.705,89.325) 82.572,90.192 ccw(c81.705,89.325) 81.705,90.551 ; 81.705,90.551 ccw(c81.705,91.777) 82.572,90.91 cw(c81.705,91.777) 81.705,90.551 ; 83.522,51.054 cw(c83.522,52.28) 82.655,51.413 ccw(c83.522,52.28) 83.522,51.054 ; 83.522,51.054 ccw(c83.522,49.828) 82.655,50.695 cw(c83.522,49.828) 83.522,51.054 ; 83.61,51.054 cw(c83.61,49.828) 84.477,50.695 ccw(c83.61,49.828) 83.61,51.054 ; 83.61,51.054 ccw(c83.61,52.28) 84.477,51.413 cw(c83.61,52.28) 83.61,51.054 ; 84.157,90.551 cw(c84.157,91.777) 83.29,90.91 ccw(c84.157,91.777) 84.157,90.551 ; 84.157,90.551 ccw(c84.157,89.325) 83.29,90.192 cw(c84.157,89.325) 84.157,90.551 ; 84.245,90.551 cw(c84.245,89.325) 85.112,90.192 ccw(c84.245,89.325) 84.245,90.551 ; 84.245,90.551 ccw(c84.245,91.777) 85.112,90.91 cw(c84.245,91.777) 84.245,90.551 ; C34.2@85.344,78.232 ccw(c85.56,79.41) 86.406,78.563 cw(c85.56,79.41) C34.2@85.344,78.232 ; C34.2@85.344,78.232 ccw(c83.811,79.765) 85.979,79.765 cw(c83.811,79.765) C34.2@85.344,78.232 ; 85.979,80.608 cw(c86.397,80.608) 86.101,80.904 ccw(c86.397,80.608) 85.979,80.608 ; 85.979,80.608 ccw(c85.561,80.608) 85.857,80.904 cw(c85.561,80.608) 85.979,80.608 ; 86.062,51.054 cw(c86.062,52.28) 85.195,51.413 ccw(c86.062,52.28) 86.062,51.054 ; 86.062,51.054 ccw(c86.062,49.828) 85.195,50.695 cw(c86.062,49.828) 86.062,51.054 ; 86.15,51.054 cw(c86.15,49.828) 87.017,50.695 ccw(c86.15,49.828) 86.15,51.054 ; 86.15,51.054 ccw(c86.15,52.28) 87.017,51.413 cw(c86.15,52.28) 86.15,51.054 ; 87.091,79.248 cw(c85.771,80.568) 85.435,78.732 ccw(c85.771,80.568) 87.091,79.248 ; 87.376,63.71 cw(c86.15,63.71) 87.017,62.843 ccw(c86.15,63.71) 87.376,63.71 ; 87.376,63.71 ccw(c88.602,63.71) 87.735,62.843 cw(c88.602,63.71) 87.376,63.71 ; 87.376,63.798 cw(c88.602,63.798) 87.735,64.665 ccw(c88.602,63.798) 87.376,63.798 ; 87.376,63.798 ccw(c86.15,63.798) 87.017,64.665 cw(c86.15,63.798) 87.376,63.798 ; 87.376,66.084 cw(c88.602,66.084) 87.735,66.951 ccw(c88.602,66.084) 87.376,66.084 ; 87.376,66.084 ccw(c86.15,66.084) 87.017,66.951 cw(c86.15,66.084) 87.376,66.084 ; 87.376,66.25 cw(c86.15,66.25) 87.017,65.383 ccw(c86.15,66.25) 87.376,66.25 ; 87.376,66.25 ccw(c88.602,66.25) 87.735,65.383 cw(c88.602,66.25) 87.376,66.25 ; 87.376,68.536 cw(c86.15,68.536) 87.017,67.669 ccw(c86.15,68.536) 87.376,68.536 ; 87.376,68.536 ccw(c88.602,68.536) 87.735,67.669 cw(c88.602,68.536) 87.376,68.536 ; 87.376,68.624 cw(c88.602,68.624) 87.735,69.491 ccw(c88.602,68.624) 87.376,68.624 ; 87.376,68.624 ccw(c86.15,68.624) 87.017,69.491 cw(c86.15,68.624) 87.376,68.624 ; 87.376,71.076 cw(c86.15,71.076) 87.017,70.209 ccw(c86.15,71.076) 87.376,71.076 ; 87.376,71.076 ccw(c88.602,71.076) 87.735,70.209 cw(c88.602,71.076) 87.376,71.076 ; 87.376,71.164 cw(c88.602,71.164) 87.735,72.031 ccw(c88.602,71.164) 87.376,71.164 ; 87.376,71.164 ccw(c86.15,71.164) 87.017,72.031 cw(c86.15,71.164) 87.376,71.164 ; 90.331,102.523 cw(c91.821,101.032) 91.821,103.14 ccw(c91.821,101.032) 90.331,102.523 ; 90.331,102.523 ccw(c88.84,104.013) 90.948,104.013 cw(c88.84,104.013) 90.331,102.523 ; 90.764,102.956 cw(c91.821,101.9) 91.821,103.394 ccw(c91.821,101.9) 90.764,102.956 ; 90.764,102.956 ccw(c89.708,104.013) 91.202,104.013 cw(c89.708,104.013) 90.764,102.956 ; 91.611,47.625 cw(c91.611,46.399) 92.478,47.266 ccw(c91.611,46.399) 91.611,47.625 ; 91.611,47.625 ccw(c91.611,48.851) 92.478,47.984 cw(c91.611,48.851) 91.611,47.625 ; 92.031,47.625 cw(c92.031,48.851) 91.164,47.984 ccw(c92.031,48.851) 92.031,47.625 ; 92.031,47.625 ccw(c92.031,46.399) 91.164,47.266 cw(c92.031,46.399) 92.031,47.625 ; 94.063,47.625 cw(c94.063,48.851) 93.196,47.984 ccw(c94.063,48.851) 94.063,47.625 ; 94.063,47.625 ccw(c94.063,46.399) 93.196,47.266 cw(c94.063,46.399) 94.063,47.625 ; 94.151,47.625 cw(c94.151,46.399) 95.018,47.266 ccw(c94.151,46.399) 94.151,47.625 ; 94.151,47.625 ccw(c94.151,48.851) 95.018,47.984 cw(c94.151,48.851) 94.151,47.625 ; 96.603,47.625 cw(c96.603,48.851) 95.736,47.984 ccw(c96.603,48.851) 96.603,47.625 ; 96.603,47.625 ccw(c96.603,46.399) 95.736,47.266 cw(c96.603,46.399) 96.603,47.625 ; 96.691,47.625 cw(c96.691,46.399) 97.558,47.266 ccw(c96.691,46.399) 96.691,47.625 ; 96.691,47.625 ccw(c96.691,48.851) 97.558,47.984 cw(c96.691,48.851) 96.691,47.625 ; 102.108,73.616 cw(c100.882,73.616) 101.749,72.749 ccw(c100.882,73.616) 102.108,73.616 ; 102.108,73.616 ccw(c103.334,73.616) 102.467,72.749 cw(c103.334,73.616) 102.108,73.616 ; 102.108,73.704 cw(c103.334,73.704) 102.467,74.571 ccw(c103.334,73.704) 102.108,73.704 ; 102.108,73.704 ccw(c100.882,73.704) 101.749,74.571 cw(c100.882,73.704) 102.108,73.704 ; 102.108,76.156 cw(c100.882,76.156) 101.749,75.289 ccw(c100.882,76.156) 102.108,76.156 ; 102.108,76.156 ccw(c103.334,76.156) 102.467,75.289 cw(c103.334,76.156) 102.108,76.156 ; 102.108,76.244 cw(c103.334,76.244) 102.467,77.111 ccw(c103.334,76.244) 102.108,76.244 ; 102.108,76.244 ccw(c100.882,76.244) 101.749,77.111 cw(c100.882,76.244) 102.108,76.244 ; 102.108,78.696 cw(c100.882,78.696) 101.749,77.829 ccw(c100.882,78.696) 102.108,78.696 ; 102.108,78.696 ccw(c103.334,78.696) 102.467,77.829 cw(c103.334,78.696) 102.108,78.696 ; 102.108,78.784 cw(c103.334,78.784) 102.467,79.651 ccw(c103.334,78.784) 102.108,78.784 ; 102.108,78.784 ccw(c100.882,78.784) 101.749,79.651 cw(c100.882,78.784) 102.108,78.784 ; 102.108,81.236 cw(c100.882,81.236) 101.749,80.369 ccw(c100.882,81.236) 102.108,81.236 ; 102.108,81.236 ccw(c103.334,81.236) 102.467,80.369 cw(c103.334,81.236) 102.108,81.236 ; 102.108,81.324 cw(c103.334,81.324) 102.467,82.191 ccw(c103.334,81.324) 102.108,81.324 ; 102.108,81.324 ccw(c100.882,81.324) 101.749,82.191 cw(c100.882,81.324) 102.108,81.324 ; 102.108,83.776 cw(c100.882,83.776) 101.749,82.909 ccw(c100.882,83.776) 102.108,83.776 ; 102.108,83.776 ccw(c103.334,83.776) 102.467,82.909 cw(c103.334,83.776) 102.108,83.776 ; 102.108,83.864 cw(c103.334,83.864) 102.467,84.731 ccw(c103.334,83.864) 102.108,83.864 ; 102.108,83.864 ccw(c100.882,83.864) 101.749,84.731 cw(c100.882,83.864) 102.108,83.864 ; 102.108,86.316 cw(c100.882,86.316) 101.749,85.449 ccw(c100.882,86.316) 102.108,86.316 ; 102.108,86.316 ccw(c103.334,86.316) 102.467,85.449 cw(c103.334,86.316) 102.108,86.316 ; 102.108,86.404 cw(c103.334,86.404) 102.467,87.271 ccw(c103.334,86.404) 102.108,86.404 ; 102.108,86.404 ccw(c100.882,86.404) 101.749,87.271 cw(c100.882,86.404) 102.108,86.404 ; 102.108,88.856 cw(c100.882,88.856) 101.749,87.989 ccw(c100.882,88.856) 102.108,88.856 ; 102.108,88.856 ccw(c103.334,88.856) 102.467,87.989 cw(c103.334,88.856) 102.108,88.856 ; 102.108,88.944 cw(c103.334,88.944) 102.467,89.811 ccw(c103.334,88.944) 102.108,88.944 ; 102.108,88.944 ccw(c100.882,88.944) 101.749,89.811 cw(c100.882,88.944) 102.108,88.944 ; 34.557,45.466 ccw(c34.557,47.993) 36.344,46.206 cw(c34.557,47.993) 34.557,45.466 ; 35.17,45.466 ccw(c35.17,47.38) 36.523,46.027 cw(c35.17,47.38) 35.17,45.466 ; 35.783,45.466 ccw(c35.783,46.767) 36.703,45.847 cw(c35.783,46.767) 35.783,45.466 ; C58.1@36.957,37.592 cw(c36.957,36.672) 37.607,37.323 ccw(c36.957,36.672) C58.1@36.957,37.592 ; C58.1@37.211,38.1 ccw(c38.131,38.1) 37.48,37.45 cw(c38.131,38.1) C58.1@37.211,38.1 ; C58.1@37.465,38.1 ccw(c38.998,38.1) 37.914,37.016 cw(c38.998,38.1) C58.1@37.465,38.1 ; 37.852,37.078 cw(c36.335,35.56) 38.481,35.56 ccw(c36.335,35.56) 37.852,37.078 ; 38.286,36.644 cw(c37.202,35.56) 38.735,35.56 ccw(c37.202,35.56) 38.286,36.644 ; 38.72,36.21 cw(c38.069,35.56) 38.989,35.56 ccw(c38.069,35.56) 38.72,36.21 ; C60.1@38.772,36.158 ccw(c38.989,36.375) 38.989,36.068 cw(c38.989,36.375) C60.1@38.772,36.158 ; 56.934,94.488 ccw(c56.934,95.339) 57.536,94.737 cw(c56.934,95.339) 56.934,94.488 ; C45.2@70.231,89.789 cw(c70.231,87.643) 71.749,89.16 ccw(c70.231,87.643) C45.2@70.231,89.789 ; C45.2@70.231,90.043 cw(c70.231,88.51) 71.315,89.594 ccw(c70.231,88.51) C45.2@70.231,90.043 ; C45.2@70.231,90.297 cw(c70.231,89.377) 70.881,90.028 ccw(c70.231,89.377) C45.2@70.231,90.297 ; C45.2@70.739,90.297 ccw(c71.046,90.297) 70.829,90.08 cw(c71.046,90.297) C45.2@70.739,90.297 ; 77.343,61.251 ccw(c78.015,61.251) 77.54,60.776 cw(c78.015,61.251) 77.343,61.251 ; 77.343,61.864 ccw(c78.628,61.864) 77.719,60.955 cw(c78.628,61.864) 77.343,61.864 ; C34.2@84.985,78.591 ccw(c82.585,80.991) 85.979,80.991 cw(c82.585,80.991) C34.2@84.985,78.591 ; C34.2@85.164,78.412 ccw(c83.198,80.378) 85.979,80.378 cw(c83.198,80.378) C34.2@85.164,78.412 ; C34.2@85.298,77.982 ccw(c85.454,78.831) 86.064,78.221 cw(c85.454,78.831) C34.2@85.298,77.982 ; C34.2@85.39,78.482 ccw(c85.665,79.989) 86.749,78.906 cw(c85.665,79.989) C34.2@85.39,78.482 ; C34.2@85.524,78.052 ccw(c84.424,79.152) 85.979,79.152 cw(c84.424,79.152) C34.2@85.524,78.052 ; C84.1@87.376,50.419 cw(c87.376,48.886) 88.46,49.97 ccw(c87.376,48.886) C84.1@87.376,50.419 ; C84.1@87.376,50.673 cw(c87.376,49.753) 88.026,50.404 ccw(c87.376,49.753) C84.1@87.376,50.673 ; v1@87.757,100.376 ccw(c87.757,101.407) 88.486,100.678 cw(c87.757,101.407) v1@87.757,100.376 ; C84.1@87.884,50.927 ccw(c88.804,50.927) 88.153,50.277 cw(c88.804,50.927) C84.1@87.884,50.927 ; 89.042,78.882 ccw(c89.758,79.598) 90.201,78.689 cw(c89.758,79.598) 89.042,78.882 ; 89.294,78.631 ccw(c89.923,79.259) 90.313,78.46 cw(c89.923,79.259) 89.294,78.631 ; 89.546,78.379 ccw(c90.088,78.921) 90.424,78.232 cw(c90.088,78.921) 89.546,78.379 ; 89.721,48.709 ccw(c90.805,49.793) 90.805,48.26 cw(c90.805,49.793) 89.721,48.709 ; 90.028,48.402 cw(c89.377,47.752) 90.297,47.752 ccw(c89.377,47.752) 90.028,48.402 ; 90.155,48.275 ccw(c90.805,48.926) 90.805,48.006 cw(c90.805,48.926) 90.155,48.275
  other v1: 77.597,60.833 80.518,98.806 51.308,100.838
WAKE: 
pads on no net: J9.4 J9.5 J9.6 J10.6 J12.4 J12.5 J12.6 P1.0 P1.1 P1.4 U7.16 U7.18 U7.20 U7.25 U7.26 U7.47 U7.48 U7.49 U7.50 U7.51 U7.52 U7.53 U7.64 U7.65 U7.66 U7.67 U7.74 U7.75 U7.81 U7.82 U7.88 U7.89 U7.96 U7.97 U7.98 U7.99 U7.100 U7.110 U7.111 U7.112 U7.113 U7.114 U7.115 U7.116 U7.133 U7.134 U7.135 U7.136 U7.137 U7.138 U7.142 U7.145 U7.148 U7.149 U7.150 U7.151 U7.152 U7.153 U7.156 U7.157 U7.158 U7.161 U7.162 U7.163 U7.164 U7.165 U7.168 U7.175 U9.9 U9.10 U9.11 U9.12 U9.13 U9.14 U9.15 U11.5 U13.1 U13.2 U13.7 U13.8 U13.13 U13.14 U13.15 U13.16 U13.19 U13.20 U13.21 U13.26 U13.27

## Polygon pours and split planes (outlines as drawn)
VSS on Top Layer "Top Layer-No Net" (hatched 90Degree grid 0.508 track 0.203, remove dead copper, pour order 1000): 27.305,112.522 27.305,27.94 28.321,26.924 29.718,28.321 111.76,28.321 111.76,112.522 111.125,113.157
VSS on Bottom Layer "Top Layer-No Net" (hatched 90Degree grid 0.508 track 0.203, remove dead copper, pour order 1001): 25.654,112.141 25.4,111.887 25.4,26.67 114.808,26.67 115.189,26.289 112.776,28.702 112.776,112.903

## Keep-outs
Keep-Out Layer:
  lines w0.254: 29.746,30 30.254,30 ; 30,29.746 30,30.254 30,29.972
  lines w0.5: 34.417,109.982 34.417,105.537 30,105.537 30,105.029 30,79.502 44.704,79.502 44.704,57.912 30,57.912 30,34.036 34.544,34.036 34.544,29.972 105.537,29.972 105.537,34.036 110.363,34.036 110.363,99.695 110.363,105.664 105.537,105.664 105.537,109.982 ; 34.417,110.236 105.537,110.236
